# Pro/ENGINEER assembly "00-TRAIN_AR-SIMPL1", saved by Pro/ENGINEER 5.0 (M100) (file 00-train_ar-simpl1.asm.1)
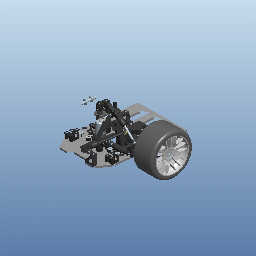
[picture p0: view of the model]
Units: millimeter Newton Second (mmNs); MM, TONNE, HOURS

Other components: 02_CHASSIS_AR_SI1, 01-TRIANGLE_SUP-AR_SI1, 01-TRIANGLE_INF-ARD_SI1, 01-FUSEE_AR_SI1, 01_BASCULEUR_SUSP-ARD_SI1, TIR_BASC_AR_SI1, 80460500-AMORT_COURT_STD_SI1

Other named items: 01_CHASSIS_AR_01, 01_BASCULEUR_SUSP-ARD_01, 01-TRIANGLE_INF-ARD_01, 01-TRIANGLE_SUP-AR_01, 01-FUSEE_AR_01, 80656400-TIR_BASC_AR_01, 80460500-AMORT_COURT_STD_01, A-DROITE, A-DESSUS, A-FACE, A-R0, S1, S2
